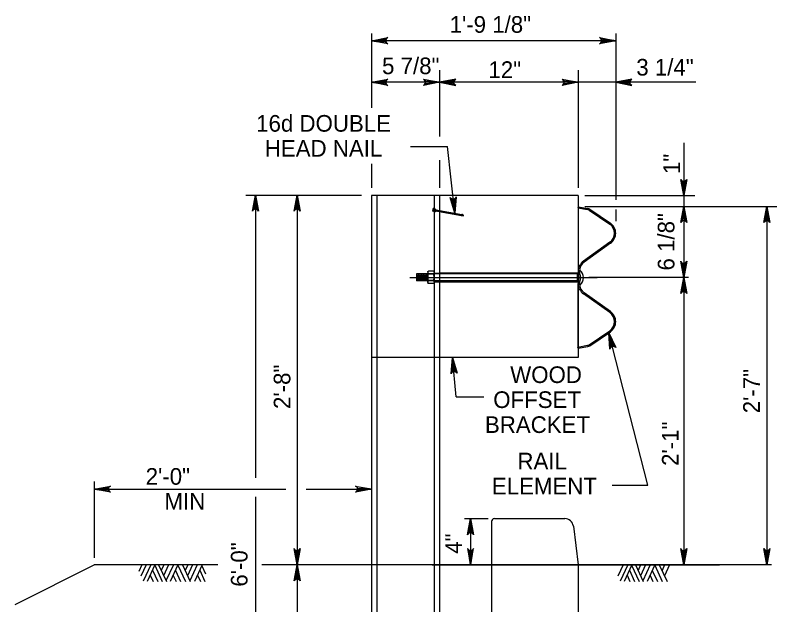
# Model space of a CAD drawing. Extents: x 632007860 to 635435983, y 295418622 to 297794622.
# Drawn here: x 632468928 to 632608434, y 295599976 to 295707901 of the extents above; entities that cross this region are included whole.
import ezdxf

# ---------------------------------------------------------------- set-up
doc = ezdxf.new("R2010")
doc.units = 0
for name, color, linetype in [('8', 7, 'Continuous'), ('C -ANNO-LABL', 7, 'Continuous'), ('S-ABUT', 7, 'Continuous'), ('S-DETL-DIMS', 7, 'Continuous'), ('S-DETL-T120', 7, 'Continuous'), ('S-GRND-MAJR', 7, 'Continuous'), ('S-STEL', 7, 'Continuous')]:
    doc.layers.add(name, color=color, linetype=linetype)

msp = doc.modelspace()

# ---------------------------------------------------------------- linework, layer by layer
at = {"layer": '8'}
msp.add_line((632541190, 295659899), (632575532, 295659899), dxfattribs=at)
at = {"layer": 'C -ANNO-LABL'}
for p, q in [((632546652, 295643805), (632546652, 295637014)), ((632545279, 295607286), (632597918, 295607286))]:
    msp.add_line(p, q, dxfattribs=at)
at = {"layer": 'S-ABUT'}
for p, q in [((632556706, 295615752), (632569592, 295615752)), ((632556178, 295615223), (632556178, 295586118)), ((632571167, 295614361), (632572053, 295607285)), ((632572053, 295607285), (632572053, 295586118))]:
    msp.add_line(p, q, dxfattribs=at)
for centre, radius, start, end in [((632556706, 295615223), 528, 90, 180), ((632569592, 295614164), 1588, 7.13073, 90)]:
    msp.add_arc(centre, radius, start, end, dxfattribs=at)
at = {"layer": 'S-DETL-DIMS'}
for p, q in [((632534216, 295704553), (632534216, 295690928)), ((632578931, 295704553), (632578931, 295674109)), ((632578931, 295703243), (632534216, 295703243)), ((632546652, 295697858), (632546652, 295685687)), ((632572053, 295697858), (632572053, 295676318)), ((632593591, 295695623), (632534216, 295695623)), ((632591392, 295684570), (632591392, 295659894)), ((632541333, 295683862), (632548112, 295683862)), ((632549477, 295671667), (632548112, 295683862)), ((632546652, 295681379), (632546652, 295676318)), ((632534216, 295680704), (632534216, 295676318)), ((632532385, 295674885), (632511146, 295674885)), ((632512942, 295674982), (632512942, 295623210)), ((632520562, 295674982), (632520562, 295607286)), ((632573301, 295674885), (632593421, 295674885)), ((632573301, 295672901), (632608434, 295672901)), ((632606632, 295672901), (632606632, 295607286)), ((632578931, 295672324), (632578931, 295670190)), ((632592258, 295659894), (632574014, 295659894)), ((632591392, 295659894), (632591392, 295607286)), ((632584813, 295621891), (632577675, 295649773)), ((632549689, 295638066), (632549054, 295645252)), ((632549689, 295638066), (632554744, 295638066)), ((632483416, 295622537), (632483416, 295608569)), ((632578268, 295621891), (632584813, 295621891)), ((632483416, 295621144), (632518512, 295621144)), ((632522223, 295621144), (632534216, 295621144)), ((632512942, 295619722), (632512942, 295567573)), ((632551214, 295615752), (632555573, 295615752)), ((632552351, 295615752), (632552351, 295607288)), ((632520562, 295607286), (632520562, 295567179))]:
    msp.add_line(p, q, dxfattribs=at)
for points in [[(632534216, 295703243), (632537176, 295703798), (632536948, 295703640), (632536830, 295703441), (632536796, 295703243), (632536830, 295703044), (632536948, 295702846), (632537176, 295702688), (632534216, 295703243), (632536948, 295702846), (632536830, 295703044), (632534216, 295703243), (632536796, 295703243), (632536830, 295703441), (632534216, 295703243), (632536948, 295703640)], [(632578931, 295703243), (632575972, 295702688), (632576200, 295702846), (632576317, 295703044), (632576351, 295703243), (632576317, 295703441), (632576200, 295703640), (632575972, 295703798), (632578931, 295703243), (632576200, 295703640), (632576317, 295703441), (632578931, 295703243), (632576351, 295703243), (632576317, 295703044), (632578931, 295703243), (632576200, 295702846)], [(632534216, 295695623), (632537176, 295696178), (632536948, 295696020), (632536830, 295695821), (632536796, 295695623), (632536830, 295695424), (632536948, 295695226), (632537176, 295695068), (632534216, 295695623), (632536948, 295695226), (632536830, 295695424), (632534216, 295695623), (632536796, 295695623), (632536830, 295695821), (632534216, 295695623), (632536948, 295696020)], [(632546652, 295695623), (632543693, 295695068), (632543921, 295695226), (632544038, 295695424), (632544073, 295695623), (632544038, 295695821), (632543921, 295696020), (632543693, 295696178), (632546652, 295695623), (632543921, 295696020), (632544038, 295695821), (632546652, 295695623), (632544073, 295695623), (632544038, 295695424), (632546652, 295695623), (632543921, 295695226)], [(632546652, 295695623), (632549612, 295695068), (632549383, 295695226), (632549266, 295695424), (632549232, 295695623), (632549266, 295695821), (632549383, 295696020), (632549612, 295696178), (632546652, 295695623), (632549383, 295696020), (632549266, 295695821), (632546652, 295695623), (632549232, 295695623), (632549266, 295695424), (632546652, 295695623), (632549383, 295695226)], [(632572053, 295695623), (632569093, 295695068), (632569321, 295695226), (632569439, 295695424), (632569473, 295695623), (632569439, 295695821), (632569321, 295696020), (632569093, 295696178), (632572053, 295695623), (632569321, 295696020), (632569439, 295695821), (632572053, 295695623), (632569473, 295695623), (632569439, 295695424), (632572053, 295695623), (632569321, 295695226)], [(632578931, 295695623), (632581890, 295695068), (632581662, 295695226), (632581545, 295695424), (632581511, 295695623), (632581545, 295695821), (632581662, 295696020), (632581890, 295696178), (632578931, 295695623), (632581662, 295696020), (632581545, 295695821), (632578931, 295695623), (632581511, 295695623), (632581545, 295695424), (632578931, 295695623), (632581662, 295695226)], [(632591392, 295674885), (632590837, 295677845), (632590995, 295677617), (632591193, 295677499), (632591392, 295677465), (632591590, 295677499), (632591789, 295677617), (632591947, 295677845), (632591392, 295674885), (632591789, 295677617), (632591590, 295677499), (632591392, 295674885), (632591392, 295677465), (632591193, 295677499), (632591392, 295674885), (632590995, 295677617)], [(632512942, 295674982), (632513496, 295672022), (632513338, 295672250), (632513140, 295672368), (632512942, 295672402), (632512743, 295672368), (632512545, 295672250), (632512387, 295672022), (632512942, 295674982), (632512545, 295672250), (632512743, 295672368), (632512942, 295674982), (632512942, 295672402), (632513140, 295672368), (632512942, 295674982), (632513338, 295672250)], [(632520562, 295674982), (632521116, 295672022), (632520958, 295672250), (632520760, 295672368), (632520562, 295672402), (632520363, 295672368), (632520165, 295672250), (632520007, 295672022), (632520562, 295674982), (632520165, 295672250), (632520363, 295672368), (632520562, 295674982), (632520562, 295672402), (632520760, 295672368), (632520562, 295674982), (632520958, 295672250)], [(632549477, 295671667), (632548596, 295674546), (632548687, 295674442), (632548778, 295674337), (632548883, 295674290), (632548989, 295674242), (632549089, 295674236), (632549190, 295674231), (632549286, 295674258), (632549383, 295674286), (632549475, 295674356), (632549567, 295674425), (632549633, 295674547), (632549699, 295674670), (632549477, 295671667), (632549633, 295674547), (632549567, 295674425), (632549477, 295671667), (632549475, 295674356), (632549383, 295674286), (632549477, 295671667), (632549286, 295674258), (632549190, 295674231), (632549477, 295671667), (632549089, 295674236), (632548989, 295674242), (632549477, 295671667), (632548883, 295674290), (632548778, 295674337), (632549477, 295671667), (632548687, 295674442)], [(632591392, 295672901), (632591947, 295669942), (632591789, 295670170), (632591590, 295670288), (632591392, 295670322), (632591193, 295670288), (632590995, 295670170), (632590837, 295669942), (632591392, 295672901), (632590995, 295670170), (632591193, 295670288), (632591392, 295672901), (632591392, 295670322), (632591590, 295670288), (632591392, 295672901), (632591789, 295670170)], [(632606632, 295672901), (632607187, 295669942), (632607029, 295670170), (632606830, 295670288), (632606632, 295670322), (632606433, 295670288), (632606235, 295670170), (632606077, 295669942), (632606632, 295672901), (632606235, 295670170), (632606433, 295670288), (632606632, 295672901), (632606632, 295670322), (632606830, 295670288), (632606632, 295672901), (632607029, 295670170)], [(632591392, 295659894), (632590837, 295662854), (632590995, 295662626), (632591193, 295662508), (632591392, 295662474), (632591590, 295662508), (632591789, 295662626), (632591947, 295662854), (632591392, 295659894), (632591789, 295662626), (632591590, 295662508), (632591392, 295659894), (632591392, 295662474), (632591193, 295662508), (632591392, 295659894), (632590995, 295662626)], [(632591392, 295659894), (632591947, 295656935), (632591868, 295657049), (632591789, 295657163), (632591689, 295657222), (632591590, 295657281), (632591491, 295657298), (632591392, 295657315), (632591293, 295657298), (632591193, 295657281), (632591094, 295657222), (632590995, 295657163), (632590916, 295657049), (632590837, 295656935), (632591392, 295659894), (632590916, 295657049), (632590995, 295657163), (632591392, 295659894), (632591094, 295657222), (632591193, 295657281), (632591392, 295659894), (632591293, 295657298), (632591392, 295657315), (632591392, 295659894), (632591491, 295657298), (632591590, 295657281), (632591392, 295659894), (632591689, 295657222), (632591789, 295657163), (632591392, 295659894), (632591868, 295657049)], [(632577675, 295649773), (632578947, 295647043), (632578842, 295647134), (632578737, 295647225), (632578626, 295647258), (632578516, 295647290), (632578415, 295647282), (632578315, 295647274), (632578223, 295647233), (632578131, 295647191), (632578050, 295647110), (632577968, 295647028), (632577920, 295646898), (632577872, 295646768), (632577675, 295649773), (632577920, 295646898), (632577968, 295647028), (632577675, 295649773), (632578050, 295647110), (632578131, 295647191), (632577675, 295649773), (632578223, 295647233), (632578315, 295647274), (632577675, 295649773), (632578415, 295647282), (632578516, 295647290), (632577675, 295649773), (632578626, 295647258), (632578737, 295647225), (632577675, 295649773), (632578842, 295647134)], [(632549054, 295645252), (632549867, 295642353), (632549779, 295642459), (632549690, 295642566), (632549586, 295642616), (632549482, 295642666), (632549381, 295642674), (632549281, 295642682), (632549184, 295642656), (632549086, 295642631), (632548993, 295642563), (632548899, 295642496), (632548830, 295642376), (632548762, 295642255), (632549054, 295645252), (632548830, 295642376), (632548899, 295642496), (632549054, 295645252), (632548993, 295642563), (632549086, 295642631), (632549054, 295645252), (632549184, 295642656), (632549281, 295642682), (632549054, 295645252), (632549381, 295642674), (632549482, 295642666), (632549054, 295645252), (632549586, 295642616), (632549690, 295642566), (632549054, 295645252), (632549779, 295642459)], [(632483416, 295621144), (632486376, 295621699), (632486148, 295621541), (632486030, 295621343), (632485996, 295621144), (632486030, 295620946), (632486148, 295620748), (632486376, 295620590), (632483416, 295621144), (632486148, 295620748), (632486030, 295620946), (632483416, 295621144), (632485996, 295621144), (632486030, 295621343), (632483416, 295621144), (632486148, 295621541)], [(632534216, 295621144), (632531257, 295620590), (632531485, 295620748), (632531603, 295620946), (632531637, 295621144), (632531603, 295621343), (632531485, 295621541), (632531257, 295621699), (632534216, 295621144), (632531485, 295621541), (632531603, 295621343), (632534216, 295621144), (632531637, 295621144), (632531603, 295620946), (632534216, 295621144), (632531485, 295620748)], [(632552351, 295615752), (632552905, 295612792), (632552826, 295612906), (632552747, 295613020), (632552648, 295613079), (632552549, 295613138), (632552450, 295613155), (632552351, 295613172), (632552251, 295613155), (632552152, 295613138), (632552053, 295613079), (632551954, 295613020), (632551875, 295612906), (632551796, 295612792), (632552351, 295615752), (632551875, 295612906), (632551954, 295613020), (632552351, 295615752), (632552053, 295613079), (632552152, 295613138), (632552351, 295615752), (632552251, 295613155), (632552351, 295613172), (632552351, 295615752), (632552450, 295613155), (632552549, 295613138), (632552351, 295615752), (632552648, 295613079), (632552747, 295613020), (632552351, 295615752), (632552826, 295612906)], [(632520562, 295607286), (632520007, 295610245), (632520165, 295610017), (632520363, 295609899), (632520562, 295609865), (632520760, 295609899), (632520958, 295610017), (632521116, 295610245), (632520562, 295607286), (632520958, 295610017), (632520760, 295609899), (632520562, 295607286), (632520562, 295609865), (632520363, 295609899), (632520562, 295607286), (632520165, 295610017)], [(632552351, 295607288), (632552905, 295610248), (632552826, 295610134), (632552747, 295610020), (632552648, 295609961), (632552549, 295609902), (632552450, 295609885), (632552351, 295609868), (632552251, 295609885), (632552152, 295609902), (632552053, 295609961), (632551954, 295610020), (632551875, 295610134), (632551796, 295610248), (632552351, 295607288), (632551875, 295610134), (632551954, 295610020), (632552351, 295607288), (632552053, 295609961), (632552152, 295609902), (632552351, 295607288), (632552251, 295609885), (632552351, 295609868), (632552351, 295607288), (632552450, 295609885), (632552549, 295609902), (632552351, 295607288), (632552648, 295609961), (632552747, 295610020), (632552351, 295607288), (632552826, 295610134)], [(632591392, 295607286), (632590837, 295610245), (632590995, 295610017), (632591193, 295609899), (632591392, 295609865), (632591590, 295609899), (632591789, 295610017), (632591947, 295610245), (632591392, 295607286), (632591789, 295610017), (632591590, 295609899), (632591392, 295607286), (632591392, 295609865), (632591193, 295609899), (632591392, 295607286), (632590995, 295610017)], [(632606632, 295607286), (632606077, 295610245), (632606235, 295610017), (632606433, 295609899), (632606632, 295609865), (632606830, 295609899), (632607029, 295610017), (632607187, 295610245), (632606632, 295607286), (632607029, 295610017), (632606830, 295609899), (632606632, 295607286), (632606632, 295609865), (632606433, 295609899), (632606632, 295607286), (632606235, 295610017)], [(632520562, 295607286), (632521116, 295604326), (632520958, 295604554), (632520760, 295604672), (632520562, 295604706), (632520363, 295604672), (632520165, 295604554), (632520007, 295604326), (632520562, 295607286), (632520165, 295604554), (632520363, 295604672), (632520562, 295607286), (632520562, 295604706), (632520760, 295604672), (632520562, 295607286), (632520958, 295604554)]]:
    msp.add_lwpolyline(points, dxfattribs=at)
at = {"layer": 'S-GRND-MAJR'}
for p, q in [((632468928, 295600017), (632483416, 295607286)), ((632506025, 295607286), (632483416, 295607286)), ((632492107, 295607289), (632491554, 295606077)), ((632492918, 295607289), (632491964, 295605200)), ((632493757, 295607289), (632492384, 295604313)), ((632494520, 295607289), (632493099, 295604208)), ((632494062, 295606307), (632495026, 295604218)), ((632494472, 295607194), (632495856, 295604218)), ((632495169, 295607289), (632496609, 295604218)), ((632496122, 295607289), (632495655, 295606259)), ((632497019, 295607289), (632496104, 295605296)), ((632497896, 295607290), (632496543, 295604371)), ((632498745, 295607290), (632497325, 295604218)), ((632498269, 295606250), (632499204, 295604219)), ((632498707, 295607204), (632500091, 295604219)), ((632499547, 295607290), (632500978, 295604219)), ((632500529, 295607290), (632500043, 295606231)), ((632501397, 295607290), (632500472, 295605297)), ((632502274, 295607290), (632500911, 295604362)), ((632503190, 295607290), (632501769, 295604219)), ((632502723, 295606279), (632503687, 295604219)), ((632503104, 295607100), (632503782, 295605650)), ((632607494, 295607286), (632514111, 295607286)), ((632580286, 295607289), (632579333, 295605200)), ((632581126, 295607289), (632579753, 295604313)), ((632581889, 295607289), (632580468, 295604208)), ((632581431, 295606307), (632582395, 295604218)), ((632581841, 295607194), (632583224, 295604218)), ((632582537, 295607289), (632583978, 295604218)), ((632583491, 295607289), (632583024, 295606259)), ((632584388, 295607290), (632583472, 295605296)), ((632585265, 295607290), (632583911, 295604371)), ((632586114, 295607290), (632584693, 295604218)), ((632585637, 295606250), (632586572, 295604219)), ((632586076, 295607204), (632587459, 295604219)), ((632586915, 295607290), (632588346, 295604219)), ((632587898, 295607290), (632587411, 295606231)), ((632588766, 295607290), (632587841, 295605297)), ((632493633, 295605381), (632494168, 295604218)), ((632497868, 295605353), (632498383, 295604218)), ((632502313, 295605392), (632502847, 295604219)), ((632581002, 295605381), (632581536, 295604218)), ((632585237, 295605354), (632585752, 295604219))]:
    msp.add_line(p, q, dxfattribs=at)
at = {"layer": 'S-STEL'}
for p, q in [((632572053, 295674885), (632534216, 295674885)), ((632534216, 295674885), (632534216, 295607286)), ((632535200, 295674885), (632535200, 295607286)), ((632545668, 295674885), (632545668, 295607286)), ((632546652, 295674885), (632546652, 295644836)), ((632572053, 295674885), (632572053, 295672854)), ((632545878, 295672068), (632545629, 295672113)), ((632545672, 295672351), (632545921, 295672306)), ((632550706, 295671201), (632545937, 295672057)), ((632545980, 295672295), (632550748, 295671438)), ((632572053, 295672854), (632572012, 295672635)), ((632572012, 295672635), (632573773, 295672311)), ((632572053, 295672854), (632573813, 295672530)), ((632572053, 295672854), (632572053, 295672628)), ((632572053, 295672628), (632572053, 295661027)), ((632574046, 295672200), (632577829, 295669644)), ((632574171, 295672384), (632577953, 295669828)), ((632574293, 295672033), (632574417, 295672217)), ((632576046, 295670849), (632576170, 295671033)), ((632577829, 295666331), (632573030, 295662868)), ((632577953, 295666147), (632573155, 295662684)), ((632575313, 295664515), (632575437, 295664331)), ((632576083, 295665071), (632576207, 295664887)), ((632574367, 295663833), (632574491, 295663648)), ((632544488, 295660570), (632542438, 295660570)), ((632542438, 295660570), (632542438, 295659248)), ((632542592, 295660367), (632542592, 295659463)), ((632542747, 295660570), (632542747, 295659248)), ((632542901, 295660367), (632542901, 295659463)), ((632543056, 295660570), (632543056, 295659248)), ((632543210, 295660367), (632543210, 295659463)), ((632543365, 295660570), (632543365, 295659248)), ((632543520, 295660367), (632543520, 295659463)), ((632543674, 295660570), (632543674, 295659248)), ((632543829, 295660367), (632543829, 295659463)), ((632543983, 295660570), (632543983, 295659248)), ((632544138, 295660367), (632544138, 295659463)), ((632544292, 295660570), (632544292, 295659248)), ((632544447, 295660367), (632544447, 295659463)), ((632544488, 295660901), (632544488, 295660768)), ((632544488, 295660768), (632544488, 295659909)), ((632572053, 295660570), (632544488, 295660570)), ((632545538, 295661054), (632544620, 295661054)), ((632545538, 295660481), (632544620, 295660481)), ((632545668, 295660702), (632546652, 295660702)), ((632545669, 295660903), (632545669, 295658914)), ((632572053, 295660702), (632546652, 295660702)), ((632571875, 295660522), (632571875, 295659200)), ((632572053, 295661027), (632572053, 295658695)), ((632572053, 295660655), (632572275, 295660655)), ((632572337, 295660512), (632572337, 295661217)), ((632572337, 295660512), (632572348, 295660512)), ((632572337, 295660512), (632572337, 295659211)), ((632572348, 295660512), (632572348, 295661217)), ((632544488, 295659248), (632542438, 295659248)), ((632544488, 295659909), (632544488, 295659049)), ((632572053, 295659248), (632544488, 295659248)), ((632544488, 295659049), (632544488, 295658916)), ((632545538, 295659336), (632544620, 295659336)), ((632545684, 295659115), (632546667, 295659115)), ((632546652, 295659115), (632572053, 295659115)), ((632572053, 295659068), (632572275, 295659068)), ((632572348, 295659211), (632572337, 295659211)), ((632572337, 295658505), (632572337, 295659211)), ((632572348, 295658505), (632572348, 295659211)), ((632545538, 295658763), (632544620, 295658763)), ((632572053, 295647161), (632572053, 295658761)), ((632572053, 295658743), (632572053, 295645252)), ((632577829, 295653457), (632573030, 295656921)), ((632577953, 295653642), (632573155, 295657105)), ((632574367, 295655956), (632574491, 295656140)), ((632575313, 295655273), (632575437, 295655458)), ((632576083, 295654717), (632576207, 295654902)), ((632572053, 295654501), (632572053, 295654275)), ((632572053, 295654322), (632572053, 295652242)), ((632574046, 295647589), (632577829, 295650145)), ((632574171, 295647405), (632577953, 295649961)), ((632576046, 295648940), (632576170, 295648756)), ((632572012, 295647153), (632573773, 295647477)), ((632572053, 295646934), (632572012, 295647153)), ((632572053, 295646934), (632573813, 295647258)), ((632572053, 295646934), (632572053, 295647161)), ((632574293, 295647756), (632574417, 295647571)), ((632572053, 295645252), (632534216, 295645252)), ((632546652, 295644836), (632546652, 295607286)), ((632534216, 295607286), (632534216, 295568152)), ((632535200, 295607286), (632535200, 295568152)), ((632545668, 295607286), (632545668, 295568152)), ((632546652, 295607286), (632546652, 295568152))]:
    msp.add_line(p, q, dxfattribs=at)
for points in [[(632545430, 295672026), (632545431, 295672032), (632545436, 295672058), (632545444, 295672102), (632545455, 295672160), (632545467, 295672228), (632545479, 295672299), (632545492, 295672367), (632545502, 295672425), (632545510, 295672469), (632545515, 295672495), (632545516, 295672501)], [(632545490, 295672015), (632545491, 295672021), (632545496, 295672047), (632545503, 295672091), (632545514, 295672150), (632545526, 295672217), (632545539, 295672288), (632545551, 295672356), (632545562, 295672414), (632545570, 295672459), (632545574, 295672485), (632545575, 295672490)], [(632545857, 295671949), (632545858, 295671955), (632545862, 295671981), (632545870, 295672025), (632545881, 295672084), (632545893, 295672151), (632545906, 295672222), (632545918, 295672290), (632545928, 295672349), (632545936, 295672393), (632545941, 295672419), (632545942, 295672425)], [(632545916, 295671939), (632545917, 295671945), (632545922, 295671970), (632545930, 295672015), (632545940, 295672073), (632545952, 295672141), (632545965, 295672212), (632545977, 295672279), (632545988, 295672338), (632545996, 295672382), (632546000, 295672408), (632546001, 295672414)], [(632550748, 295671438), (632550719, 295671274), (632550712, 295671235), (632550707, 295671210), (632550706, 295671201)], [(632551093, 295671251), (632551094, 295671254), (632551093, 295671251), (632551093, 295671248), (632551092, 295671247), (632551092, 295671246), (632551092, 295671247), (632551093, 295671248), (632551093, 295671251)], [(632551094, 295671254), (632551094, 295671256), (632551095, 295671259), (632551095, 295671260), (632551095, 295671261)]]:
    msp.add_lwpolyline(points, dxfattribs=at)
for centre, radius, start, end in [((632573642, 295671602), 722, 55.95328, 79.57099), ((632573642, 295671602), 944, 55.95161, 79.57134), ((632576710, 295667988), 1999, 304.0481, 55.9519), ((632576710, 295667988), 2221, 304.04809, 55.95191), ((632574274, 295661027), 2221, 124.04786, 180.00023), ((632574274, 295661027), 1999, 124.04776, 180.00034), ((632572272, 295660588), 65.6, 272.72166, 0.00271), ((632571349, 295659861), 1684, 306.37027, 53.62973), ((632571349, 295659861), 1192, 326.93176, 33.06824), ((632572272, 295659135), 65.6, 359.99729, 87.27835), ((632574274, 295658761), 2221, 179.99977, 235.95214), ((632574274, 295658761), 1999, 179.99966, 235.95224), ((632576710, 295651801), 1999, 304.0481, 55.9519), ((632576710, 295651801), 2221, 304.04809, 55.95191), ((632573642, 295648187), 722, 280.42901, 304.04672), ((632573642, 295648187), 944, 280.42866, 304.04839)]:
    msp.add_arc(centre, radius, start, end, dxfattribs=at)
for points, degree in [([(632545430, 295672026), (632545490, 295672015)], 1), ([(632545511, 295672134), (632545629, 295672113)], 1), ([(632545575, 295672490), (632545516, 295672501)], 1), ([(632545672, 295672351), (632545554, 295672372)], 1), ([(632545857, 295671949), (632545916, 295671939)], 1), ([(632546001, 295672414), (632545942, 295672425)], 1), ([(632550706, 295671201), (632550770, 295671209), (632550899, 295671225), (632551028, 295671239), (632551092, 295671246)], 3), ([(632551095, 295671261), (632551037, 295671290), (632550921, 295671348), (632550806, 295671408), (632550748, 295671438)], 3), ([(632544488, 295660901), (632544620, 295661054)], 1), ([(632544620, 295660481), (632544586, 295660525), (632544520, 295660607), (632544488, 295660715), (632544488, 295660767), (632544488, 295660768)], 3), ([(632544488, 295659909), (632544488, 295659922), (632544489, 295660008), (632544511, 295660168), (632544564, 295660345), (632544606, 295660448), (632544620, 295660481)], 3), ([(632545538, 295661054), (632545669, 295660903)], 1), ([(632545538, 295660481), (632545573, 295660525), (632545639, 295660607), (632545670, 295660715), (632545671, 295660767), (632545671, 295660768)], 3), ([(632545671, 295659909), (632545670, 295659922), (632545670, 295660008), (632545648, 295660168), (632545595, 295660345), (632545552, 295660448), (632545538, 295660481)], 3), ([(632545669, 295660570), (632545671, 295660570)], 1), ([(632571875, 295660522), (632572272, 295660522)], 1), ([(632572272, 295660522), (632572275, 295660523)], 1), ([(632572272, 295660522), (632572272, 295660522), (632572291, 295660522), (632572327, 295660515), (632572335, 295660486), (632572337, 295660477)], 3), ([(632572337, 295661217), (632572348, 295661217)], 1), ([(632544620, 295659336), (632544601, 295659384), (632544554, 295659499), (632544501, 295659690), (632544492, 295659835), (632544488, 295659909)], 3), ([(632544488, 295659049), (632544493, 295659090), (632544505, 295659177), (632544565, 295659269), (632544607, 295659320), (632544620, 295659336)], 3), ([(632545538, 295659336), (632545558, 295659384), (632545605, 295659499), (632545658, 295659690), (632545666, 295659835), (632545671, 295659909)], 3), ([(632545671, 295659049), (632545665, 295659090), (632545654, 295659177), (632545593, 295659269), (632545551, 295659320), (632545538, 295659336)], 3), ([(632545671, 295659248), (632545669, 295659248)], 1), ([(632572272, 295659200), (632571875, 295659200)], 1), ([(632572337, 295659246), (632572335, 295659237), (632572327, 295659208), (632572291, 295659200), (632572272, 295659200), (632572272, 295659200)], 3), ([(632572275, 295659200), (632572272, 295659200)], 1), ([(632544620, 295658763), (632544488, 295658916)], 1), ([(632545669, 295658914), (632545538, 295658763)], 1), ([(632572337, 295658571), (632572348, 295658571)], 1), ([(632572348, 295658505), (632572337, 295658505)], 1)]:
    msp.add_open_spline(points, degree=degree, dxfattribs=at)

# ---------------------------------------------------------------- texts
at = {"layer": 'S-DETL-T120'}
for s, height, p in [('1\'-9 1/8"', 3048, (632548510, 295704690)), ('5 7/8"', 3048, (632536129, 295697114)), ('12"', 3048, (632555619, 295696415)), ('3 1/4"', 3048, (632582701, 295696859)), ('16d DOUBLE', 3048.1, (632513069, 295686582)), ('HEAD NAIL', 3048.1, (632514654, 295682009)), ('WOOD', 3048.1, (632559606, 295640571)), ('OFFSET', 3048.1, (632556498, 295635999)), ('BRACKET', 3048.1, (632554974, 295631427)), ('RAIL', 3048.1, (632560928, 295624758)), ('2\'-0"', 3048.1, (632492826, 295621946)), ('ELEMENT', 3048.1, (632556248, 295620186)), ('MIN', 3048.1, (632496270, 295617374))]:
    msp.add_text(s, height=height, dxfattribs=at).set_placement(p)
for s, height, p in [('1"', 3048.1, (632590704, 295678827)), ('6 1/8"', 3048, (632589684, 295661166)), ('2\'-8"', 3048, (632519329, 295635822)), ('2\'-7"', 3048, (632605335, 295635030)), ('2\'-1"', 3048, (632590445, 295625398)), ('4"', 3048.1, (632550745, 295609305)), ('6\'-0"', 3048, (632511483, 295603284))]:
    msp.add_text(s, height=height, rotation=90, dxfattribs=at).set_placement(p)

doc.saveas('drawing.dxf')
